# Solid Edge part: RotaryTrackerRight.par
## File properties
Author: wojci
Template: ISO Metric Part.par
Last saved by: wojci
Revision: 20
Application: Solid Edge
Username: wojci
Accuracy: 0.990
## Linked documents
RotaryTracker.par
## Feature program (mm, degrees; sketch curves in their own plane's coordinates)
part copy "CopiedPart_1"
sketch used by "unnamed Cutout 1" plane through (-4.25, 0, 5.5) normal (0, -1, 0) x-axis (1, 0, 0)
  line (-4.25, -5.5) -> (-19.25, -5.5)
  line (-4.25, -5.5) -> (-4.8187, 1)
  line (-4.8187, 1) -> (-19.25, 1)
  line (-19.25, 1) -> (-19.25, -5.5)
  dimension (linear) = 19.25
  dimension (linear) = 4.25
extrude "unnamed Cutout 1" cut through along +normal
sketch for "unnamed Cutout 2" plane through (0, 0, 0) normal (1, 0, 0) x-axis (0, 1, 0)
  line (-8, 0) -> (-8.5687, 6.5)
  line (-8.5687, 6.5) -> (-15.193, 6.5)
  line (-15.193, 6.5) -> (-15.193, 0)
  line (-15.193, 0) -> (-8, 0)
  dimension (linear) = 15.193
extrude "unnamed Cutout 2" cut through along -normal
chamfer "Chamfer_1" setback 4
fillet "Round_2" radius 10
fillet "Round_4" radius 7
chamfer "Chamfer_4" setback 1.5
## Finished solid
Body 1: solid body, 29 faces, 69 edges, 41 vertices.
  Faces by surface: plane 14, cylinder 9, spline 3, swept 2, blend 1
  Edges by curve: line 30, circle 16, curve on surface 11, spline 6, intersection 5, ellipse 1
Bounding box of the edges (mm; curved faces can reach further): 31.084 x 45.394 x 12.000, from (-22.5835, -13.7771, 0) to (8.5, 31.6168, 12).
Cylindrical faces by radius (mm): R1.35 x2, R1.8 x1, R2.75 x2, R6.25 x2, R7 x1, R8.5 x1
Planar faces by outward normal: +x 3, +z 2, -x 2, -z 3, oblique 4
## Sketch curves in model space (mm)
line (-8.5, 0, 12) -> (-8.5, 0, 0)
line (-23.5, 0, 6.5) -> (-23.5, 0, 0)
line (-9.0687, 0, 6.5) -> (-23.5, 0, 6.5)
line (-8.5, 0, 0) -> (-9.0687, 0, 6.5)
line (-8.5, 0, 0) -> (-23.5, 0, 0)
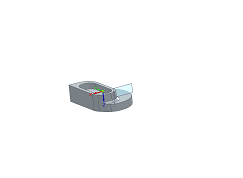
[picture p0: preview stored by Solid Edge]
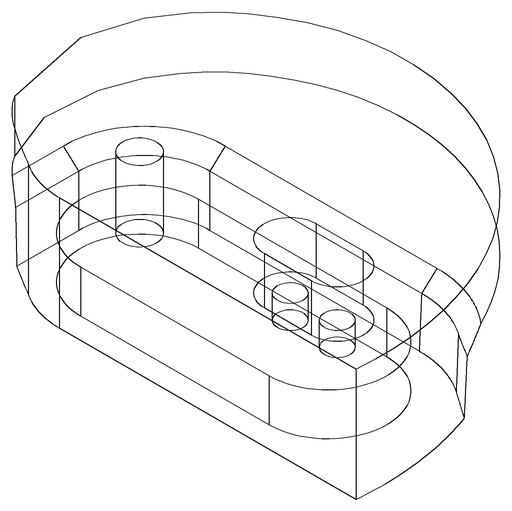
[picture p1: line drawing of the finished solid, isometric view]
